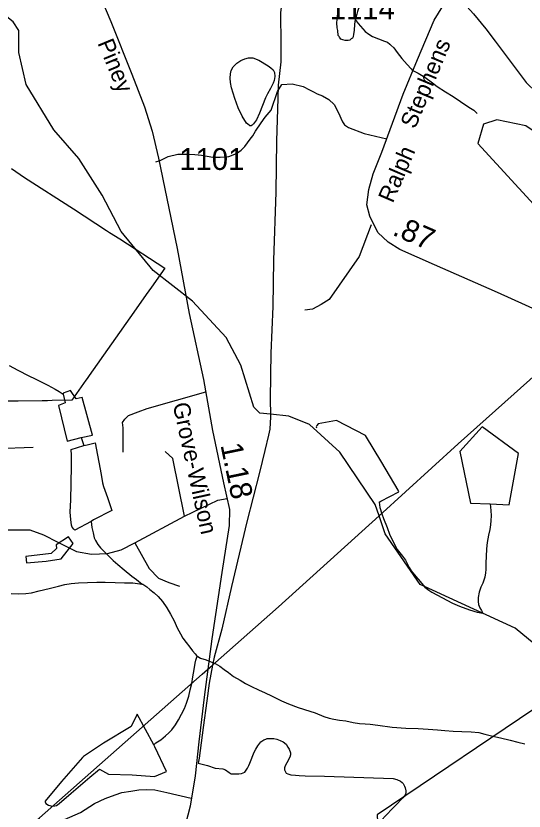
# Model space of a CAD drawing. Extents: x 2001466 to 2224147, y 644118 to 847247.
# Drawn here: x 2046367 to 2049275, y 682530 to 687083 of the extents above; entities that cross this region are included whole.
import ezdxf

# ---------------------------------------------------------------- set-up
doc = ezdxf.new("R2010")
doc.units = 0
for name, color, linetype in [('Exist Boundary Political City Limit New', 7, 'Continuous'), ('Exist Hydrographic Creek Single Shore', 7, 'Continuous'), ('Exist Hydrographic Misc Water Feature', 7, 'Continuous'), ('Exist Road Non-System Type 51', 7, 'Continuous'), ('Exist Road Secondary Mileage Hundredths English Label', 7, 'Continuous'), ('Exist Road Secondary Type 51 Attributed', 7, 'Continuous'), ('Exist Road Secondary Type 51 Label', 7, 'Continuous'), ('Exist Road Secondary Type 51 Number Label', 7, 'Continuous'), ('Exist Utilities Electrical Transmission Line', 7, 'Continuous'), ('Map Preparation Boundary City Limit Buffer Line', 7, 'Continuous')]:
    doc.layers.add(name, color=color, linetype=linetype)

msp = doc.modelspace()

# ---------------------------------------------------------------- linework, layer by layer
at = {"layer": 'Exist Boundary Political City Limit New'}
msp.add_lwpolyline([(2046342.5, 686208.4), (2046417, 686158.7), (2046695.8, 685978.1), (2046886.2, 685854.6), (2046903.2, 685843.6), (2046961.8, 685805.7), (2047218.9, 685639.1), (2047142.1, 685530.1), (2047112.8, 685488.4), (2047040.9, 685386.2), (2046785.4, 685023.4), (2046774, 685007.3), (2046767, 684997.4), (2046686.1, 684882.5), (2046575, 684880.6), (2046547.2, 684879.8), (2046517.4, 684879.4), (2046380.8, 684877.7), (2046294, 684876.6)], dxfattribs=at)
at = {"layer": 'Exist Hydrographic Creek Single Shore'}
for points in [[(2047822.9, 684802.5), (2047762.9, 684808.5), (2047728.8, 684842), (2047654, 685083.1), (2047569.9, 685242.2), (2047378, 685449.5), (2047152.9, 685624.7), (2046968.9, 685848.3), (2046860.9, 686057.2), (2046727, 686266.6), (2046584.9, 686430.3), (2046425.9, 686689.4), (2046383.9, 686874), (2046383.9, 686998.7), (2046350.9, 687048.6), (2044999, 688119.4)], [(2048444.7, 684220.5), (2048421.9, 684286.5), (2048221, 684585.9), (2048045.9, 684743.7), (2047929, 684792), (2047822.9, 684802.5)], [(2049411.6, 683170), (2049389.8, 683338.3), (2049331.9, 683487.2), (2049222.9, 683577.9), (2048680.9, 683828.5), (2048479.9, 684118), (2048444.7, 684220.5)]]:
    msp.add_lwpolyline(points, dxfattribs=at)
at = {"layer": 'Exist Hydrographic Misc Water Feature'}
msp.add_line((2046740.3, 684669.1), (2046756.5, 684623.3), dxfattribs=at)
for points in [[(2048311.6, 687263.6), (2048341.5, 687251.7), (2048355.3, 687245.6), (2048361.6, 687239.7), (2048367.6, 687229.5), (2048369.2, 687219.5), (2048369.2, 687211.9), (2048367.4, 687205.7), (2048359.2, 687197.6), (2048333.5, 687139.8), (2048321.6, 687107.5), (2048317.8, 687093.5), (2048311.8, 687073.7), (2048307.7, 687061.8)], [(2048307.7, 687061.8), (2048303.8, 687035.6), (2048301.6, 686999.8), (2048297.9, 686977.7), (2048296, 686963.7), (2048292.1, 686955.4), (2048286, 686951.5), (2048277.8, 686943.4), (2048268.1, 686941.7), (2048262.2, 686941.7), (2048249.9, 686941.6), (2048238.2, 686945.3), (2048226.1, 686949.6), (2048217.9, 686961.4), (2048216, 686965.3), (2048211.7, 686971.2), (2048209.7, 686999.6), (2048205.6, 687015.6), (2048203.9, 687043.5), (2048207.6, 687081.4), (2048209.5, 687097.3)], [(2048307.7, 687061.8), (2048325.8, 687039.6), (2048365.7, 686993.8), (2048385.8, 686977.7), (2048407.8, 686965.9), (2048442, 686951.8), (2048476.3, 686938.1), (2048492.3, 686932), (2048505.8, 686921.8), (2048512.1, 686916), (2048529.8, 686899.9), (2048548, 686874), (2048574.3, 686840), (2048606.1, 686804.4), (2048628, 686780.4), (2048634.4, 686772.1), (2048668.4, 686754.4), (2048706.3, 686732.4), (2048750.2, 686700.6), (2048778.1, 686678.5), (2048824.6, 686648.8), (2048868.3, 686620.6), (2048910.4, 686592.8), (2048940.7, 686572.8), (2048968.8, 686555.1), (2048986.6, 686543), (2049002.4, 686528.9), (2049006.7, 686525)], [(2047794.5, 686614.7), (2047760.6, 686526.6), (2047743, 686488.7), (2047727, 686464.8), (2047718.8, 686456.7), (2047712.6, 686452.8), (2047705.1, 686452.7), (2047701, 686456.6), (2047686.8, 686468.4), (2047660.8, 686508.5), (2047639, 686556.4), (2047618.7, 686610.2), (2047600.7, 686670.5), (2047594.5, 686702.3), (2047592.5, 686726.1), (2047594.7, 686752.1), (2047598.6, 686770.2), (2047610.3, 686792.3), (2047630.2, 686812.4), (2047654.6, 686828.2), (2047676.4, 686836.3), (2047698.1, 686842.3), (2047722.5, 686842.7), (2047756.3, 686828.6), (2047810.5, 686796.9), (2047826.2, 686784.7), (2047838.1, 686774.8), (2047846.1, 686759), (2047848.4, 686736.8), (2047844.5, 686712.6), (2047838.3, 686696.9), (2047822.8, 686666.8), (2047806.8, 686636.8), (2047794.5, 686614.7)], [(2049401.9, 685887.4), (2049643.8, 685928.4), (2049550.9, 686271.5), (2049284, 686454.1), (2049117.9, 686487), (2049043, 686462.3), (2049010, 686351.5), (2049351.8, 685980.3), (2049401.9, 685887.4)], [(2046327.7, 685082.1), (2046377.8, 685054.3), (2046440.1, 685022.5), (2046478, 685004.6), (2046516.2, 684986.6), (2046550.2, 684968.5), (2046592, 684946.8), (2046614, 684932.9), (2046631.8, 684920.8), (2046638, 684916.7)], [(2046638, 684916.7), (2046648.4, 684866.8), (2046609.9, 684852.8), (2046660.5, 684648.8), (2046740.3, 684669.1)], [(2046740.3, 684669.1), (2046804.5, 684683.4), (2046746, 684899.1), (2046711.8, 684890.8), (2046680, 684939.1), (2046638.2, 684922.7), (2046638, 684916.7)], [(2048445.1, 684298.2), (2048454.9, 684304.4), (2048558.7, 684358.5), (2048554.6, 684368.5), (2048460.5, 684526.3), (2048368, 684680.2), (2048202.1, 684765.8), (2048096.1, 684747.4), (2048088.1, 684737.7), (2048085.8, 684729.5), (2048086, 684725.4)], [(2049080.8, 684289.5), (2049189, 684283.6), (2049242.3, 684577.7), (2049033.8, 684729.3), (2048906.3, 684589.3), (2048968.8, 684293.5), (2049080.8, 684289.5)], [(2046797.3, 684189.2), (2046703.4, 684138.9), (2046697.6, 684145), (2046689.6, 684155.2), (2046685.1, 684167.2), (2046681.6, 684199), (2046677.5, 684241), (2046681.4, 684313), (2046682.7, 684404.9), (2046684.9, 684506.8), (2046684.5, 684568.9), (2046682.7, 684600.8), (2046756.5, 684623.3)], [(2046756.5, 684623.3), (2046774.5, 684627), (2046820.5, 684639.1), (2046854.7, 684457.5), (2046862.9, 684409.2), (2046868.9, 684389.2), (2046891, 684325.4), (2046915.2, 684251.6), (2046811.2, 684197.2), (2046797.3, 684189.2)], [(2048445.1, 684298.2), (2048449, 684268.4), (2048461.3, 684232.5), (2048470.9, 684206.3), (2048491.2, 684154.5), (2048505.2, 684116.3), (2048529.4, 684064.4), (2048549.3, 684028.5), (2048579.6, 683990.7), (2048595.4, 683966.8), (2048617.3, 683924.9), (2048627.6, 683906.7), (2048655.5, 683872.9), (2048679.7, 683844.9), (2048705.9, 683812.9), (2048729.7, 683795.1), (2048747.5, 683783.1), (2048779.9, 683767.2), (2048831.8, 683737), (2048865.7, 683721.4), (2048905.6, 683703.5), (2048961.8, 683683.3), (2049005.9, 683669.7), (2049038.1, 683663.6)], [(2049080.8, 684289.5), (2049084.6, 684251.5), (2049086.9, 684221.6), (2049084.6, 684193.5), (2049082.8, 684169.9), (2049079.1, 684141.7), (2049071.1, 684109.6), (2049063.3, 684067.4), (2049059.4, 684031.5), (2049057.2, 683987.6), (2049055.5, 683951.7), (2049055.5, 683913.6), (2049053.5, 683893.7), (2049049.4, 683869.5), (2049037.7, 683835.6), (2049027.8, 683811.5), (2049017.6, 683783.5), (2049011.9, 683753.6), (2049011.7, 683729.6), (2049014.1, 683713.5), (2049021.7, 683693.6), (2049030.1, 683679.4), (2049038.1, 683663.6)], [(2046797.3, 684189.2), (2046801.4, 684153.3), (2046809.6, 684123.2), (2046815.5, 684095.1), (2046821.5, 684079.2), (2046835.6, 684057.2), (2046851.8, 684037.3), (2046877.7, 684011.5), (2046924, 683965.5), (2046949.9, 683941.7), (2046985.9, 683911.5), (2047029.8, 683875.7), (2047057.9, 683855.6), (2047089.8, 683830.3), (2047094, 683829.8)], [(2046539.7, 683960.9), (2046625.5, 683975.1), (2046693.7, 684062.9), (2046667.3, 684101), (2046597.6, 684054.8), (2046599.4, 684033), (2046568, 684004.9), (2046423.7, 683988.6), (2046428, 683952.4), (2046539.7, 683960.9)], [(2046340, 683776.7), (2046380.4, 683774.6), (2046424.1, 683776.5), (2046456.3, 683780.5), (2046500, 683790.9), (2046556.4, 683804.7), (2046610.1, 683818.9), (2046646, 683827.2), (2046683.9, 683833.2), (2046725.7, 683837), (2046775.8, 683839.1), (2046830.3, 683841.4), (2046878.3, 683841.5), (2046935.7, 683839.6), (2046988.2, 683837.8), (2047036.2, 683837.8), (2047076, 683831.7), (2047089.8, 683830.3), (2047094, 683829.8)], [(2047094, 683829.8), (2047115.9, 683813.9), (2047134, 683799.8), (2047158, 683780), (2047180.1, 683758), (2047206.2, 683730.1), (2047230.2, 683694), (2047252.3, 683658.2), (2047272.4, 683620.3), (2047290.4, 683580.2), (2047308.5, 683544.2), (2047322.4, 683520.2), (2047340.5, 683496.3), (2047362.6, 683468.2), (2047376.8, 683448.3), (2047392.6, 683430.4), (2047400.6, 683420.7), (2047404.7, 683416.4)], [(2047155.7, 682910.3), (2047167.6, 682920.3), (2047195.7, 682938.3), (2047223.6, 682960.4), (2047241.4, 682978.4), (2047259.3, 682996.4), (2047279.2, 683024.2), (2047297.6, 683052.2), (2047315.3, 683084.4), (2047331, 683118.5), (2047343.3, 683148.3), (2047357.3, 683188.4), (2047364.9, 683224.5), (2047373.1, 683260.6), (2047379, 683298.6), (2047386.8, 683340.5), (2047392.8, 683376.5), (2047396.7, 683394.6), (2047400.8, 683406.5), (2047404.7, 683416.4)], [(2047404.7, 683416.4), (2047408.6, 683414.7), (2047422.9, 683406.4), (2047454.9, 683396.7), (2047478.7, 683386.6), (2047506.8, 683374.6), (2047533, 683360.9), (2047558.7, 683340.8), (2047582.8, 683322.9), (2047612.8, 683301), (2047650.7, 683279), (2047680.9, 683261), (2047714.9, 683243.2), (2047754.9, 683225.4), (2047793, 683207.4), (2047828.7, 683189.5), (2047886.9, 683161.6), (2047926.9, 683143.4), (2047981.1, 683123.8), (2048049.1, 683101.7), (2048079.1, 683091.9), (2048129.3, 683072.1), (2048159, 683061.9), (2048185.3, 683056.3), (2048217.5, 683050.2), (2048255, 683046.2), (2048297, 683038.2), (2048332.9, 683032.3), (2048364.9, 683030.3), (2048393.2, 683028.4), (2048437.3, 683022.6), (2048518.9, 683010.6), (2048597, 683004.8), (2048669, 683003.2), (2048725.4, 682999.2), (2048779.1, 682995.5), (2048821, 682991.5), (2048869.1, 682987.5), (2048919, 682985.6), (2048971.5, 682983.7), (2049014.9, 682979.6), (2049049.4, 682971.5), (2049094.9, 682959.7), (2049139.2, 682949.8), (2049195.2, 682936), (2049239.5, 682924), (2049279, 682914.4)], [(2047155.7, 682910.3), (2047061.4, 683086.1), (2047025.5, 683014), (2046867.8, 682919.5), (2046754, 682843.4), (2046747.9, 682837.5), (2046628.3, 682699.1), (2046534.4, 682587.2), (2046534.6, 682583.1), (2046538.5, 682573.2), (2046554.1, 682565.1), (2046574.4, 682559.2), (2046588.8, 682561.1), (2046598.4, 682563.2), (2046614.6, 682573), (2046682.3, 682633.3), (2046790.1, 682723.6), (2046845.7, 682769.5), (2046895.9, 682741.6), (2047031.9, 682738), (2047160.2, 682728.3), (2047227.7, 682756.2), (2047161.7, 682898), (2047155.7, 682910.3)]]:
    msp.add_lwpolyline(points, dxfattribs=at)
at = {"layer": 'Exist Road Non-System Type 51'}
msp.add_line((2047415.3, 682833.9), (2047409.2, 682804), dxfattribs=at)
for points in [[(2048295.7, 688403.4), (2048212.1, 688161.8), (2048124.6, 687895.6), (2048033.3, 687633.4), (2047954.7, 687407), (2047929.1, 687329.6), (2047916.1, 687283.8), (2047903.2, 687236.1), (2047887.7, 687164.4), (2047880.4, 687100.5), (2047882.1, 686921.6), (2047882.1, 686819.6), (2047868, 686686.8)], [(2048833.7, 687263.1), (2048984.3, 687094.1), (2049056.5, 687008.6), (2049109.1, 686937.5), (2049165.6, 686862.4), (2049241.5, 686762.8), (2049268.7, 686724.2), (2049286.3, 686701.9), (2049307.9, 686681.4), (2049325.5, 686665.1), (2049349.1, 686644.6), (2049370.9, 686632.2)], [(2047167.5, 686247.4), (2047191.7, 686254.9), (2047239, 686277.9), (2047293.3, 686291.5), (2047344.8, 686291.5), (2047391, 686288.8), (2047429, 686286.1), (2047494.1, 686274.7), (2047536.1, 686273.8), (2047564.1, 686275.3), (2047586.2, 686278.8), (2047628.5, 686296), (2047654.9, 686313.4), (2047677.3, 686335), (2047708.2, 686376.3), (2047722.6, 686396), (2047737.1, 686423.8), (2047770.9, 686470.7), (2047792.6, 686503.3), (2047827.9, 686544), (2047864.5, 686650.8), (2047887.6, 686691.1)], [(2047887.6, 686691.1), (2047946.7, 686694.4), (2048010, 686679.6), (2048047.3, 686659.9), (2048069.5, 686648.4), (2048090.9, 686637.7), (2048120.5, 686624.5), (2048156.6, 686604.8), (2048188.7, 686576), (2048214.2, 686524.2), (2048226.5, 686497.9), (2048234.7, 686477.3), (2048247.9, 686460), (2048269.2, 686444.4), (2048360.3, 686408.8), (2048488.5, 686378.8)], [(2047868, 686686.8), (2047866.4, 686610.8), (2047857.4, 686367), (2047853.4, 686073.1), (2047841.5, 685685.3), (2047836.1, 685419.4), (2047824.6, 685151.6), (2047824.1, 685027.6), (2047821.2, 684885.7), (2047822.9, 684802.5)], [(2048398.7, 685886.1), (2048330.8, 685704.8), (2048159.1, 685459.9), (2048114.1, 685430.2), (2048063.5, 685404.3), (2048019.9, 685398.9)], [(2046981.4, 684585.5), (2046981.4, 684723.6), (2046977.7, 684754.5), (2046990.4, 684774.5), (2047010.4, 684794.5), (2047066.7, 684816.3), (2047117.6, 684834.5), (2047453.2, 684931)], [(2047822.9, 684802.5), (2047823.2, 684787.7), (2047819.7, 684717.7), (2047813, 684681.9), (2047791.2, 684594.3), (2047760.7, 684468.9), (2047688.9, 684186.4), (2047601.3, 683816.2), (2047544.3, 683571.3), (2047501.1, 683412.2), (2047492, 683365.5)], [(2045786.9, 684581), (2045840.2, 684591.6), (2046465.1, 684612.9)], [(2047331.4, 684218.6), (2047264, 684549), (2047221.4, 684588.1)], [(2047331.4, 684218.6), (2047523.2, 684310.9), (2047575.4, 684319.7)], [(2047047.4, 684065.8), (2047331.4, 684218.6)], [(2045943.2, 684126.2), (2046010.6, 684140.4), (2046447.3, 684140.4), (2046525.4, 684112), (2046607.1, 684069.3), (2046713.6, 684016), (2046798.8, 684001.8), (2046891.2, 684005.4), (2046969.3, 684026.7), (2047047.4, 684065.8)], [(2047047.4, 684065.8), (2047129, 683920.1), (2047182.3, 683863.3), (2047242.7, 683838.4), (2047303, 683817.1)], [(2047492, 683365.5), (2047472, 683262.8), (2047459.9, 683161), (2047438.9, 683009.4), (2047415.3, 682833.9)], [(2047566.4, 682766.2), (2047586.3, 682750.3), (2047598.1, 682743.4), (2047624, 682742.8), (2047642.1, 682744.5), (2047658.1, 682746.1), (2047676.3, 682753.8), (2047684.5, 682763.6), (2047692.7, 682775.4), (2047699, 682791.3), (2047705.3, 682805.2), (2047730.6, 682866.7), (2047738.9, 682884.5), (2047751.3, 682904.2), (2047767.8, 682925.9), (2047786, 682937.5), (2047796.1, 682941.3), (2047804.2, 682945.2), (2047824.2, 682946.8), (2047842.2, 682946.4), (2047860.1, 682942), (2047879.9, 682933.6), (2047895.8, 682927.3), (2047913.5, 682912.9), (2047923.2, 682896.7), (2047930.9, 682884.6), (2047938.5, 682864.4), (2047938.3, 682852.4), (2047934, 682838.5), (2047917.4, 682806.9), (2047907, 682789.1), (2047902.8, 682777.2), (2047904.5, 682767.1), (2047910.3, 682755), (2047914.1, 682746.9), (2047922.1, 682742.8), (2047940, 682738.4), (2047965.9, 682735.9), (2047987.9, 682733.4), (2048021.8, 682732.7), (2048131.8, 682730.5), (2048525.5, 682716.5), (2048547.4, 682712), (2048567.2, 682701.6), (2048577.1, 682693.4), (2048582.9, 682687.3), (2048590.6, 682673.1), (2048594.4, 682663.1), (2048598.1, 682647), (2048597.9, 682639), (2048595.7, 682625), (2048581.3, 682605.3), (2048536.3, 682560.2), (2048520, 682542.6), (2048454.8, 682475.3)], [(2047409.2, 682804), (2047462.9, 682792.1), (2047506.7, 682776.1), (2047550.5, 682772.2), (2047566.4, 682766.2)], [(2046464.9, 682452.4), (2046490.6, 682454), (2046526.2, 682457.2), (2046561.5, 682463.6), (2046645, 682482.9), (2046736.5, 682523), (2046816.7, 682572.8), (2046877.7, 682601.7), (2046935.5, 682624.2), (2046974, 682637.1), (2047025.4, 682645.1), (2047070.4, 682651.5), (2047112.1, 682654.8), (2047161.9, 682651.5), (2047230.9, 682637.1), (2047370.6, 682603.3)]]:
    msp.add_lwpolyline(points, dxfattribs=at)
at = {"layer": 'Exist Road Secondary Type 51 Attributed'}
for points in [[(2046734.7, 687467.8), (2046909.4, 687051.6), (2047030.8, 686748.5), (2047102.6, 686562.5), (2047145.8, 686423.1), (2047182.3, 686268.9), (2047289.4, 685751.3), (2047358.5, 685379.5), (2047440.9, 685001.3), (2047492.1, 684709.8), (2047555.4, 684409.8), (2047589.2, 684257.6), (2047587.1, 684164.7), (2047545.4, 683896.4), (2047487.3, 683516.1), (2047443.5, 683183.4), (2047414, 682927.7), (2047391.8, 682732.3), (2047363.3, 682559.1), (2047323.7, 682403.8), (2047229.2, 682103.8), (2047176.5, 681901), (2047151.1, 681789), (2047132.1, 681655.9)], [(2048375.6, 686000.6), (2048386.7, 686088.3), (2048412, 686178), (2048460.6, 686303.7), (2048583.6, 686634.4), (2048664.8, 686833), (2048760.4, 687058), (2048810, 687139.3), (2048868, 687203.7), (2048927.8, 687248.6), (2048999, 687290.5), (2049075.3, 687319.3), (2049181.9, 687373.2)], [(2051180.3, 685412.2), (2051147.6, 685392.1), (2051104.3, 685357.3), (2051031.5, 685329.8), (2050956.5, 685315), (2050746.5, 685307.6), (2050486.3, 685302.4), (2050348, 685289.7), (2050160.1, 685265.4), (2049951.6, 685240), (2049800.7, 685240), (2049700.4, 685253.8), (2049582.2, 685290.7), (2049122.4, 685499.9), (2048761.4, 685657.3), (2048563.5, 685746), (2048497, 685788.3), (2048437.9, 685842.1), (2048392.5, 685936.1), (2048375.6, 686000.6)]]:
    msp.add_lwpolyline(points, dxfattribs=at)
at = {"layer": 'Exist Utilities Electrical Transmission Line'}
msp.add_line((2047432.9, 683313.4), (2047492, 683365.5), dxfattribs=at)
for points in [[(2048444.7, 684220.5), (2048898.2, 684632.3), (2049575, 685237.4), (2049633.4, 685294)], [(2047492, 683365.5), (2047870.3, 683698.9), (2048444.7, 684220.5)], [(2046461.3, 682457.7), (2046501.1, 682492.3), (2047432.9, 683313.4)], [(2049411.6, 683170), (2048434, 682508.2), (2048472, 681708.3)]]:
    msp.add_lwpolyline(points, dxfattribs=at)
at = {"layer": 'Map Preparation Boundary City Limit Buffer Line'}
msp.add_lwpolyline([(2046342.5, 686208.4), (2046417, 686158.7), (2046695.8, 685978.1), (2046886.2, 685854.6), (2046903.2, 685843.6), (2046961.8, 685805.7), (2047218.9, 685639.1), (2047142.1, 685530.1), (2047112.8, 685488.4), (2047040.9, 685386.2), (2046785.4, 685023.4), (2046774, 685007.3), (2046767, 684997.4), (2046686.1, 684882.5), (2046575, 684880.6), (2046547.2, 684879.8), (2046517.4, 684879.4), (2046380.8, 684877.7), (2046294, 684876.6)], dxfattribs=at)

# ---------------------------------------------------------------- texts
at = {"layer": 'Exist Road Secondary Mileage Hundredths English Label'}
for s, rotation, p in [('.87', 336.4441, (2048515.3, 685831.2)), ('1.18', 281.7311, (2047536.9, 684626.1))]:
    msp.add_text(s, height=125, rotation=rotation, dxfattribs=at).set_placement(p)
at = {"layer": 'Exist Road Secondary Type 51 Label'}
for s, rotation, p in [('Piney', 292.4589, (2046832.3, 686927.9)), ('Stephens', 67.4451, (2048651, 686431.7)), ('Ralph', 66.6645, (2048523.2, 686006.8)), ('Grove-Wilson', 282.3665, (2047263.2, 684859.7))]:
    msp.add_text(s, height=95, rotation=rotation, dxfattribs=at).set_placement(p)
at = {"layer": 'Exist Road Secondary Type 51 Number Label'}
for s, p in [('1114', (2048162.8, 687063.9)), ('1101', (2047301.8, 686201))]:
    msp.add_text(s, height=125, dxfattribs=at).set_placement(p)

doc.saveas('drawing.dxf')
